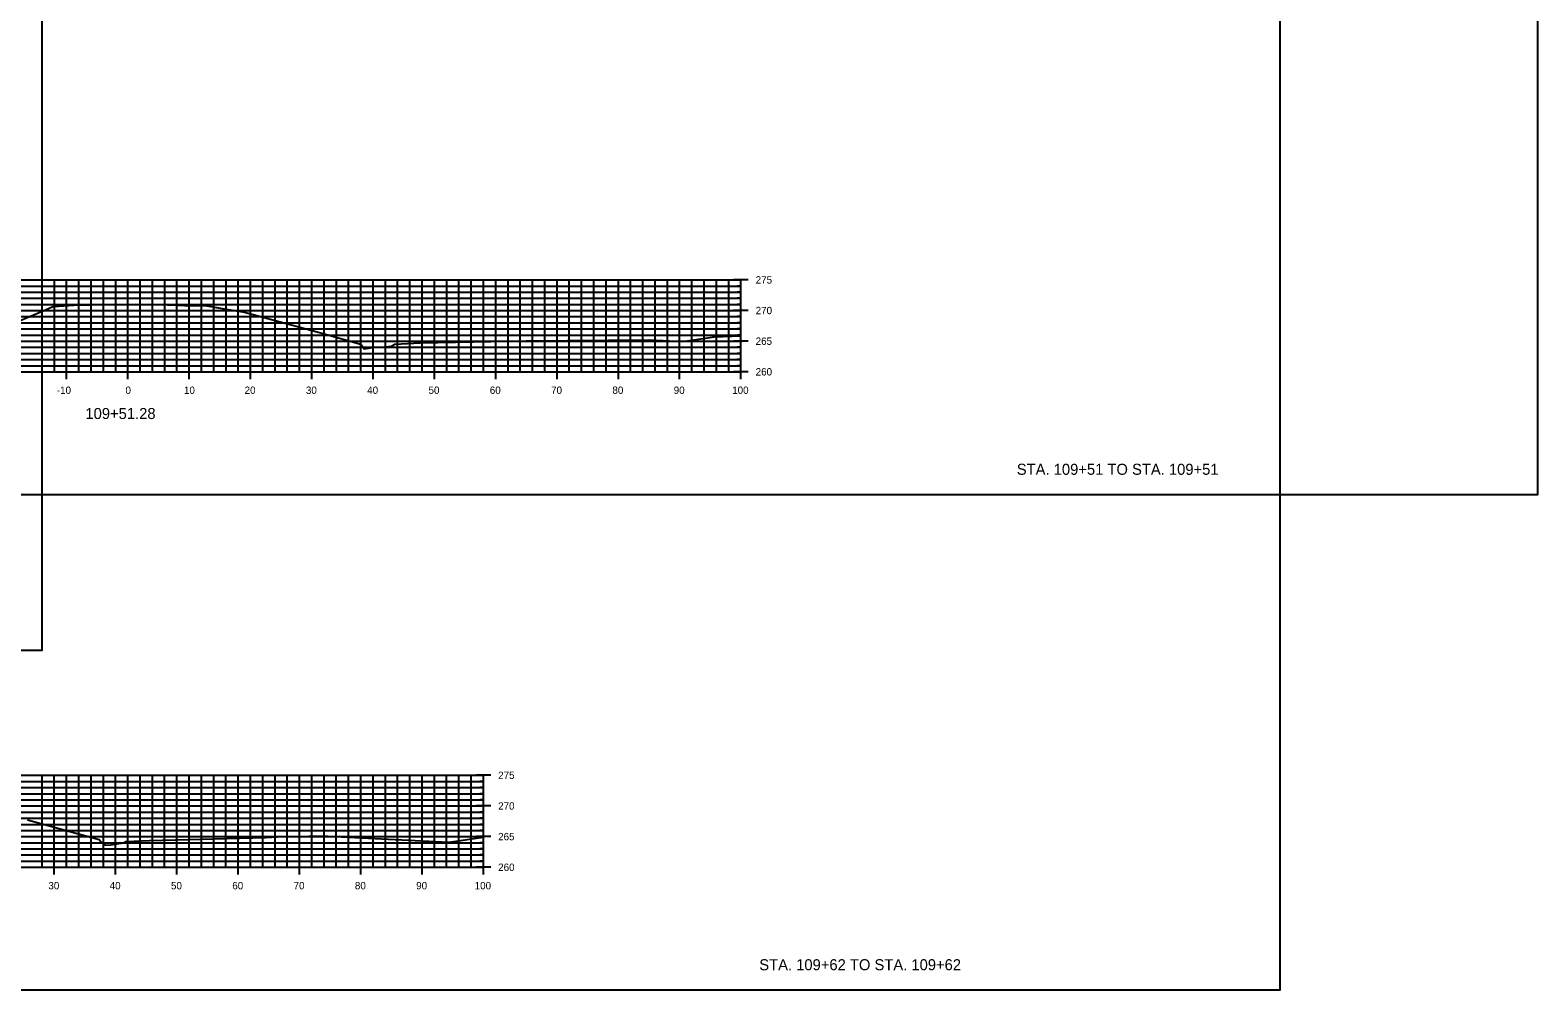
# Model space of a CAD drawing. Extents: x 1661012 to 1662122, y 670053 to 671852.
# Drawn here: x 1661390.7 to 1661636.6, y 671488.8 to 671645.4 of the extents above; entities that cross this region are included whole.
import ezdxf

# ---------------------------------------------------------------- set-up
doc = ezdxf.new("R2010")
doc.units = 0
for name, color, linetype in [('R_Concrete', 7, 'Continuous'), ('R_Concrete Hidden', 7, 'Continuous'), ('R_Erosion', 7, 'Continuous'), ('R_Exist Surface', 7, 'Continuous'), ('R_Proposed Road', 7, 'Continuous')]:
    doc.layers.add(name, color=color, linetype=linetype)

msp = doc.modelspace()

# ---------------------------------------------------------------- linework, layer by layer
at = {"layer": 'R_Concrete'}
for p, q in [((1661306.65, 671604.66), (1661506.65, 671604.66)), ((1661306.65, 671603.66), (1661506.65, 671603.66)), ((1661306.65, 671602.66), (1661506.65, 671602.66)), ((1661392.65, 671589.66), (1661392.65, 671604.66)), ((1661394.65, 671589.66), (1661394.65, 671604.66)), ((1661396.65, 671589.66), (1661396.65, 671604.66)), ((1661398.65, 671589.66), (1661398.65, 671604.66)), ((1661400.65, 671589.66), (1661400.65, 671604.66)), ((1661402.65, 671589.66), (1661402.65, 671604.66)), ((1661404.65, 671589.66), (1661404.65, 671604.66)), ((1661406.65, 671589.66), (1661406.65, 671604.66)), ((1661408.65, 671589.66), (1661408.65, 671604.66)), ((1661410.65, 671589.66), (1661410.65, 671604.66)), ((1661412.65, 671589.66), (1661412.65, 671604.66)), ((1661414.65, 671589.66), (1661414.65, 671604.66)), ((1661416.65, 671589.66), (1661416.65, 671604.66)), ((1661418.65, 671589.66), (1661418.65, 671604.66)), ((1661420.65, 671589.66), (1661420.65, 671604.66)), ((1661422.65, 671589.66), (1661422.65, 671604.66)), ((1661424.65, 671589.66), (1661424.65, 671604.66)), ((1661426.65, 671589.66), (1661426.65, 671604.66)), ((1661428.65, 671589.66), (1661428.65, 671604.66)), ((1661430.65, 671589.66), (1661430.65, 671604.66)), ((1661432.65, 671589.66), (1661432.65, 671604.66)), ((1661434.65, 671589.66), (1661434.65, 671604.66)), ((1661436.65, 671589.66), (1661436.65, 671604.66)), ((1661438.65, 671589.66), (1661438.65, 671604.66)), ((1661440.65, 671589.66), (1661440.65, 671604.66)), ((1661442.65, 671589.66), (1661442.65, 671604.66)), ((1661444.65, 671589.66), (1661444.65, 671604.66)), ((1661446.65, 671589.66), (1661446.65, 671604.66)), ((1661448.65, 671589.66), (1661448.65, 671604.66)), ((1661450.65, 671589.66), (1661450.65, 671604.66)), ((1661452.65, 671589.66), (1661452.65, 671604.66)), ((1661454.65, 671589.66), (1661454.65, 671604.66)), ((1661456.65, 671589.66), (1661456.65, 671604.66)), ((1661458.65, 671589.66), (1661458.65, 671604.66)), ((1661460.65, 671589.66), (1661460.65, 671604.66)), ((1661462.65, 671589.66), (1661462.65, 671604.66)), ((1661464.65, 671589.66), (1661464.65, 671604.66)), ((1661466.65, 671589.66), (1661466.65, 671604.66)), ((1661468.65, 671589.66), (1661468.65, 671604.66)), ((1661470.65, 671589.66), (1661470.65, 671604.66)), ((1661472.65, 671589.66), (1661472.65, 671604.66)), ((1661474.65, 671589.66), (1661474.65, 671604.66)), ((1661476.65, 671589.66), (1661476.65, 671604.66)), ((1661478.65, 671589.66), (1661478.65, 671604.66)), ((1661480.65, 671589.66), (1661480.65, 671604.66)), ((1661482.65, 671589.66), (1661482.65, 671604.66)), ((1661484.65, 671589.66), (1661484.65, 671604.66)), ((1661486.65, 671589.66), (1661486.65, 671604.66)), ((1661488.65, 671589.66), (1661488.65, 671604.66)), ((1661490.65, 671589.66), (1661490.65, 671604.66)), ((1661492.65, 671589.66), (1661492.65, 671604.66)), ((1661494.65, 671589.66), (1661494.65, 671604.66)), ((1661496.65, 671589.66), (1661496.65, 671604.66)), ((1661498.65, 671589.66), (1661498.65, 671604.66)), ((1661500.65, 671589.66), (1661500.65, 671604.66)), ((1661502.65, 671589.66), (1661502.65, 671604.66)), ((1661504.65, 671589.66), (1661504.65, 671604.66)), ((1661507.85, 671604.66), (1661505.45, 671604.66)), ((1661506.65, 671603.66), (1661506.05, 671603.66)), ((1661506.65, 671602.66), (1661506.05, 671602.66)), ((1661506.65, 671589.66), (1661506.65, 671604.66)), ((1661306.65, 671601.66), (1661506.65, 671601.66)), ((1661306.65, 671600.66), (1661506.65, 671600.66)), ((1661506.65, 671601.66), (1661506.05, 671601.66)), ((1661506.65, 671600.66), (1661506.05, 671600.66)), ((1661306.65, 671599.66), (1661506.65, 671599.66)), ((1661306.65, 671598.66), (1661506.65, 671598.66)), ((1661507.85, 671599.66), (1661505.45, 671599.66)), ((1661506.65, 671598.66), (1661506.05, 671598.66)), ((1661306.65, 671597.66), (1661506.65, 671597.66)), ((1661306.65, 671596.66), (1661506.65, 671596.66)), ((1661306.65, 671595.66), (1661506.65, 671595.66)), ((1661506.65, 671597.66), (1661506.05, 671597.66)), ((1661506.65, 671596.66), (1661506.05, 671596.66)), ((1661506.65, 671595.66), (1661506.05, 671595.66)), ((1661306.65, 671594.66), (1661506.65, 671594.66)), ((1661306.65, 671593.66), (1661506.65, 671593.66)), ((1661507.85, 671594.66), (1661505.45, 671594.66)), ((1661506.65, 671593.66), (1661506.05, 671593.66)), ((1661306.65, 671592.66), (1661506.65, 671592.66)), ((1661306.65, 671591.66), (1661506.65, 671591.66)), ((1661306.65, 671590.66), (1661506.65, 671590.66)), ((1661396.65, 671588.46), (1661396.65, 671590.86)), ((1661406.65, 671588.46), (1661406.65, 671590.86)), ((1661416.65, 671588.46), (1661416.65, 671590.86)), ((1661426.65, 671588.46), (1661426.65, 671590.86)), ((1661436.65, 671588.46), (1661436.65, 671590.86)), ((1661446.65, 671588.46), (1661446.65, 671590.86)), ((1661456.65, 671588.46), (1661456.65, 671590.86)), ((1661466.65, 671588.46), (1661466.65, 671590.86)), ((1661476.65, 671588.46), (1661476.65, 671590.86)), ((1661486.65, 671588.46), (1661486.65, 671590.86)), ((1661496.65, 671588.46), (1661496.65, 671590.86)), ((1661506.65, 671592.66), (1661506.05, 671592.66)), ((1661506.65, 671591.66), (1661506.05, 671591.66)), ((1661506.65, 671590.66), (1661506.05, 671590.66)), ((1661506.65, 671588.46), (1661506.65, 671590.86)), ((1661306.65, 671589.66), (1661506.65, 671589.66)), ((1661392.65, 671589.66), (1661392.65, 671590.26)), ((1661394.65, 671589.66), (1661394.65, 671590.26)), ((1661398.65, 671589.66), (1661398.65, 671590.26)), ((1661400.65, 671589.66), (1661400.65, 671590.26)), ((1661402.65, 671589.66), (1661402.65, 671590.26)), ((1661404.65, 671589.66), (1661404.65, 671590.26)), ((1661408.65, 671589.66), (1661408.65, 671590.26)), ((1661410.65, 671589.66), (1661410.65, 671590.26)), ((1661412.65, 671589.66), (1661412.65, 671590.26)), ((1661414.65, 671589.66), (1661414.65, 671590.26)), ((1661418.65, 671589.66), (1661418.65, 671590.26)), ((1661420.65, 671589.66), (1661420.65, 671590.26)), ((1661422.65, 671589.66), (1661422.65, 671590.26)), ((1661424.65, 671589.66), (1661424.65, 671590.26)), ((1661428.65, 671589.66), (1661428.65, 671590.26)), ((1661430.65, 671589.66), (1661430.65, 671590.26)), ((1661432.65, 671589.66), (1661432.65, 671590.26)), ((1661434.65, 671589.66), (1661434.65, 671590.26)), ((1661438.65, 671589.66), (1661438.65, 671590.26)), ((1661440.65, 671589.66), (1661440.65, 671590.26)), ((1661442.65, 671589.66), (1661442.65, 671590.26)), ((1661444.65, 671589.66), (1661444.65, 671590.26)), ((1661448.65, 671589.66), (1661448.65, 671590.26)), ((1661450.65, 671589.66), (1661450.65, 671590.26)), ((1661452.65, 671589.66), (1661452.65, 671590.26)), ((1661454.65, 671589.66), (1661454.65, 671590.26)), ((1661458.65, 671589.66), (1661458.65, 671590.26)), ((1661460.65, 671589.66), (1661460.65, 671590.26)), ((1661462.65, 671589.66), (1661462.65, 671590.26)), ((1661464.65, 671589.66), (1661464.65, 671590.26)), ((1661468.65, 671589.66), (1661468.65, 671590.26)), ((1661470.65, 671589.66), (1661470.65, 671590.26)), ((1661472.65, 671589.66), (1661472.65, 671590.26)), ((1661474.65, 671589.66), (1661474.65, 671590.26)), ((1661478.65, 671589.66), (1661478.65, 671590.26)), ((1661480.65, 671589.66), (1661480.65, 671590.26)), ((1661482.65, 671589.66), (1661482.65, 671590.26)), ((1661484.65, 671589.66), (1661484.65, 671590.26)), ((1661488.65, 671589.66), (1661488.65, 671590.26)), ((1661490.65, 671589.66), (1661490.65, 671590.26)), ((1661492.65, 671589.66), (1661492.65, 671590.26)), ((1661494.65, 671589.66), (1661494.65, 671590.26)), ((1661498.65, 671589.66), (1661498.65, 671590.26)), ((1661500.65, 671589.66), (1661500.65, 671590.26)), ((1661502.65, 671589.66), (1661502.65, 671590.26)), ((1661504.65, 671589.66), (1661504.65, 671590.26)), ((1661507.85, 671589.66), (1661505.45, 671589.66)), ((1661264.64, 671523.84), (1661464.64, 671523.84)), ((1661264.64, 671522.84), (1661464.64, 671522.84)), ((1661264.64, 671521.84), (1661464.64, 671521.84)), ((1661392.64, 671508.84), (1661392.64, 671523.84)), ((1661394.64, 671508.84), (1661394.64, 671523.84)), ((1661396.64, 671508.84), (1661396.64, 671523.84)), ((1661398.64, 671508.84), (1661398.64, 671523.84)), ((1661400.64, 671508.84), (1661400.64, 671523.84)), ((1661402.64, 671508.84), (1661402.64, 671523.84)), ((1661404.64, 671508.84), (1661404.64, 671523.84)), ((1661406.64, 671508.84), (1661406.64, 671523.84)), ((1661408.64, 671508.84), (1661408.64, 671523.84)), ((1661410.64, 671508.84), (1661410.64, 671523.84)), ((1661412.64, 671508.84), (1661412.64, 671523.84)), ((1661414.64, 671508.84), (1661414.64, 671523.84)), ((1661416.64, 671508.84), (1661416.64, 671523.84)), ((1661418.64, 671508.84), (1661418.64, 671523.84)), ((1661420.64, 671508.84), (1661420.64, 671523.84)), ((1661422.64, 671508.84), (1661422.64, 671523.84)), ((1661424.64, 671508.84), (1661424.64, 671523.84)), ((1661426.64, 671508.84), (1661426.64, 671523.84)), ((1661428.64, 671508.84), (1661428.64, 671523.84)), ((1661430.64, 671508.84), (1661430.64, 671523.84)), ((1661432.64, 671508.84), (1661432.64, 671523.84)), ((1661434.64, 671508.84), (1661434.64, 671523.84)), ((1661436.64, 671508.84), (1661436.64, 671523.84)), ((1661438.64, 671508.84), (1661438.64, 671523.84)), ((1661440.64, 671508.84), (1661440.64, 671523.84)), ((1661442.64, 671508.84), (1661442.64, 671523.84)), ((1661444.64, 671508.84), (1661444.64, 671523.84)), ((1661446.64, 671508.84), (1661446.64, 671523.84)), ((1661448.64, 671508.84), (1661448.64, 671523.84)), ((1661450.64, 671508.84), (1661450.64, 671523.84)), ((1661452.64, 671508.84), (1661452.64, 671523.84)), ((1661454.64, 671508.84), (1661454.64, 671523.84)), ((1661456.64, 671508.84), (1661456.64, 671523.84)), ((1661458.64, 671508.84), (1661458.64, 671523.84)), ((1661460.64, 671508.84), (1661460.64, 671523.84)), ((1661462.64, 671508.84), (1661462.64, 671523.84)), ((1661465.84, 671523.84), (1661463.44, 671523.84)), ((1661464.64, 671522.84), (1661464.04, 671522.84)), ((1661464.64, 671521.84), (1661464.04, 671521.84)), ((1661464.64, 671508.84), (1661464.64, 671523.84)), ((1661264.64, 671520.84), (1661464.64, 671520.84)), ((1661264.64, 671519.84), (1661464.64, 671519.84)), ((1661464.64, 671520.84), (1661464.04, 671520.84)), ((1661464.64, 671519.84), (1661464.04, 671519.84)), ((1661264.64, 671518.84), (1661464.64, 671518.84)), ((1661264.64, 671517.84), (1661464.64, 671517.84)), ((1661264.64, 671516.84), (1661464.64, 671516.84)), ((1661465.84, 671518.84), (1661463.44, 671518.84)), ((1661464.64, 671517.84), (1661464.04, 671517.84)), ((1661464.64, 671516.84), (1661464.04, 671516.84)), ((1661264.64, 671515.84), (1661464.64, 671515.84)), ((1661264.64, 671514.84), (1661464.64, 671514.84)), ((1661464.64, 671515.84), (1661464.04, 671515.84)), ((1661464.64, 671514.84), (1661464.04, 671514.84)), ((1661264.64, 671513.84), (1661464.64, 671513.84)), ((1661264.64, 671512.84), (1661464.64, 671512.84)), ((1661264.64, 671511.84), (1661464.64, 671511.84)), ((1661465.84, 671513.84), (1661463.44, 671513.84)), ((1661464.64, 671512.84), (1661464.04, 671512.84)), ((1661464.64, 671511.84), (1661464.04, 671511.84)), ((1661264.64, 671510.84), (1661464.64, 671510.84)), ((1661264.64, 671509.84), (1661464.64, 671509.84)), ((1661392.64, 671508.84), (1661392.64, 671509.44)), ((1661394.64, 671507.64), (1661394.64, 671510.04)), ((1661396.64, 671508.84), (1661396.64, 671509.44)), ((1661398.64, 671508.84), (1661398.64, 671509.44)), ((1661400.64, 671508.84), (1661400.64, 671509.44)), ((1661402.64, 671508.84), (1661402.64, 671509.44)), ((1661404.64, 671507.64), (1661404.64, 671510.04)), ((1661406.64, 671508.84), (1661406.64, 671509.44)), ((1661408.64, 671508.84), (1661408.64, 671509.44)), ((1661410.64, 671508.84), (1661410.64, 671509.44)), ((1661412.64, 671508.84), (1661412.64, 671509.44)), ((1661414.64, 671507.64), (1661414.64, 671510.04)), ((1661416.64, 671508.84), (1661416.64, 671509.44)), ((1661418.64, 671508.84), (1661418.64, 671509.44)), ((1661420.64, 671508.84), (1661420.64, 671509.44)), ((1661422.64, 671508.84), (1661422.64, 671509.44)), ((1661424.64, 671507.64), (1661424.64, 671510.04)), ((1661426.64, 671508.84), (1661426.64, 671509.44)), ((1661428.64, 671508.84), (1661428.64, 671509.44)), ((1661430.64, 671508.84), (1661430.64, 671509.44)), ((1661432.64, 671508.84), (1661432.64, 671509.44)), ((1661434.64, 671507.64), (1661434.64, 671510.04)), ((1661436.64, 671508.84), (1661436.64, 671509.44)), ((1661438.64, 671508.84), (1661438.64, 671509.44)), ((1661440.64, 671508.84), (1661440.64, 671509.44)), ((1661442.64, 671508.84), (1661442.64, 671509.44)), ((1661444.64, 671507.64), (1661444.64, 671510.04)), ((1661446.64, 671508.84), (1661446.64, 671509.44)), ((1661448.64, 671508.84), (1661448.64, 671509.44)), ((1661450.64, 671508.84), (1661450.64, 671509.44)), ((1661452.64, 671508.84), (1661452.64, 671509.44)), ((1661454.64, 671507.64), (1661454.64, 671510.04)), ((1661456.64, 671508.84), (1661456.64, 671509.44)), ((1661458.64, 671508.84), (1661458.64, 671509.44)), ((1661460.64, 671508.84), (1661460.64, 671509.44)), ((1661462.64, 671508.84), (1661462.64, 671509.44)), ((1661464.64, 671510.84), (1661464.04, 671510.84)), ((1661464.64, 671509.84), (1661464.04, 671509.84)), ((1661464.64, 671507.64), (1661464.64, 671510.04)), ((1661264.64, 671508.84), (1661464.64, 671508.84)), ((1661465.84, 671508.84), (1661463.44, 671508.84))]:
    msp.add_line(p, q, dxfattribs=at)
at = {"layer": 'R_Erosion'}
for points in [[(1661388.06, 671597.62), (1661393.22, 671599.79), (1661394.41, 671600.29), (1661394.5, 671600.3), (1661397.8, 671600.56), (1661403.3, 671600.66), (1661407.81, 671600.72), (1661413.11, 671600.57), (1661417.29, 671600.44), (1661418.25, 671600.49), (1661419.19, 671600.5), (1661421.77, 671600.06), (1661425.65, 671599.37), (1661437.88, 671596.06), (1661444.41, 671594.23), (1661444.81, 671593.95), (1661445.21, 671593.41), (1661446.67, 671593.61), (1661448.1, 671593.66), (1661448.71, 671593.71), (1661449.58, 671593.85), (1661450.17, 671594.16), (1661454.33, 671594.4), (1661471.59, 671594.72), (1661491.74, 671594.89), (1661497.1, 671594.62), (1661502.34, 671595.35), (1661506.65, 671595.54)], [(1661390.25, 671516.56), (1661401.96, 671513.34), (1661402.35, 671512.88), (1661402.92, 671512.46), (1661403.86, 671512.52), (1661405.14, 671512.7), (1661405.94, 671512.83), (1661406.31, 671513.02), (1661410.19, 671513.19), (1661429.14, 671513.67), (1661430.97, 671513.81), (1661436.15, 671513.9), (1661439.3, 671513.93), (1661458.99, 671512.95), (1661464.64, 671513.73)]]:
    msp.add_lwpolyline(points, dxfattribs=at)
at = {"layer": 'R_Exist Surface'}
for p, q in [((1661506.65, 671589.66), (1661506.65, 671604.66)), ((1661306.65, 671589.66), (1661506.65, 671589.66)), ((1661464.64, 671508.84), (1661464.64, 671523.84)), ((1661264.64, 671508.84), (1661464.64, 671508.84))]:
    msp.add_line(p, q, dxfattribs=at)
at = {"layer": 'R_Proposed Road'}
for points in [[(1661276.65, 671569.66), (1661636.65, 671569.66), (1661636.65, 671762.36), (1661276.65, 671762.36)], [(1661032.67, 671544.25), (1661392.67, 671544.25), (1661392.67, 671736.95), (1661032.67, 671736.95)], [(1661234.64, 671488.84), (1661594.64, 671488.84), (1661594.64, 671681.54), (1661234.64, 671681.54)]]:
    msp.add_lwpolyline(points, close=True, dxfattribs=at)

# ---------------------------------------------------------------- texts
at = {"layer": 'R_Concrete Hidden'}
for s, height, p in [('275', 1.2, (1661509.05, 671604.06)), ('270', 1.2, (1661509.05, 671599.06)), ('265', 1.2, (1661509.05, 671594.06)), ('260', 1.2, (1661509.05, 671589.06)), ('-10', 1.2, (1661395.05, 671586.06)), ('0', 1.2, (1661406.25, 671586.06)), ('10', 1.2, (1661415.79, 671586.06)), ('20', 1.2, (1661425.68, 671586.06)), ('30', 1.2, (1661435.68, 671586.06)), ('40', 1.2, (1661445.68, 671586.06)), ('50', 1.2, (1661455.68, 671586.06)), ('60', 1.2, (1661465.68, 671586.06)), ('70', 1.2, (1661475.68, 671586.06)), ('80', 1.2, (1661485.68, 671586.06)), ('90', 1.2, (1661495.68, 671586.06)), ('100', 1.2, (1661505.22, 671586.06)), ('109+51.28', 1.8, (1661399.71, 671581.96)), ('STA. 109+51 TO STA. 109+51', 1.8, (1661551.65, 671572.86)), ('275', 1.2, (1661467.04, 671523.24)), ('270', 1.2, (1661467.04, 671518.24)), ('265', 1.2, (1661467.04, 671513.24)), ('260', 1.2, (1661467.04, 671508.24)), ('30', 1.2, (1661393.67, 671505.24)), ('40', 1.2, (1661403.67, 671505.24)), ('50', 1.2, (1661413.67, 671505.24)), ('60', 1.2, (1661423.67, 671505.24)), ('70', 1.2, (1661433.67, 671505.24)), ('80', 1.2, (1661443.67, 671505.24)), ('90', 1.2, (1661453.67, 671505.24)), ('100', 1.2, (1661463.21, 671505.24)), ('STA. 109+62 TO STA. 109+62', 1.8, (1661509.64, 671492.04))]:
    msp.add_text(s, height=height, dxfattribs=at).set_placement(p)

doc.saveas('drawing.dxf')
